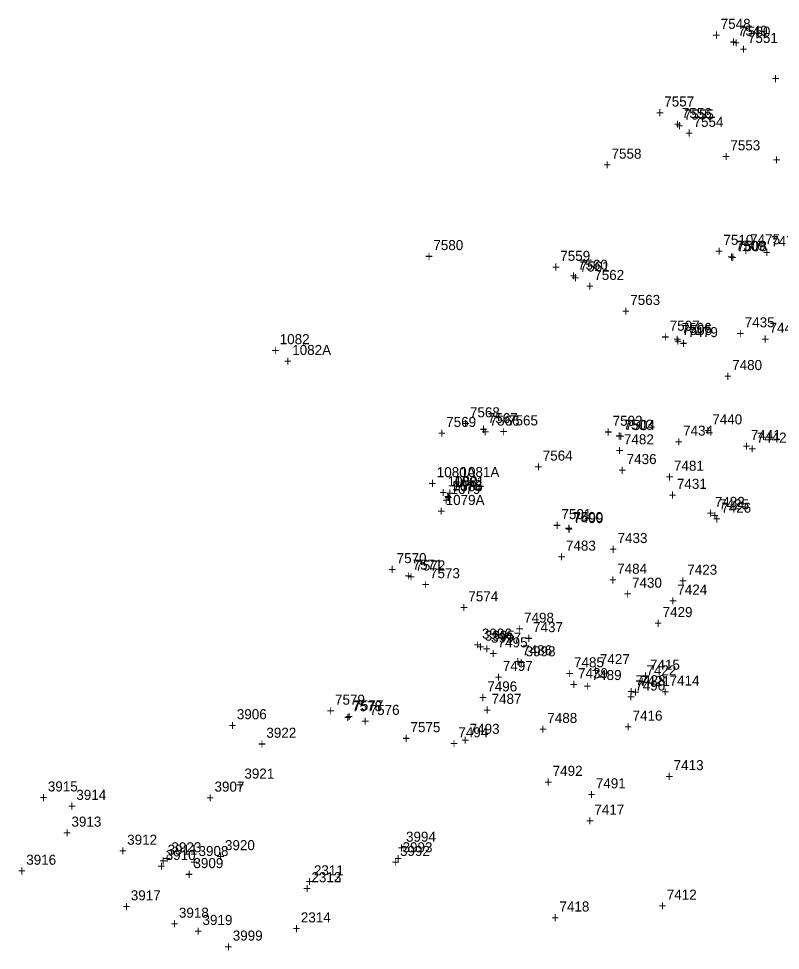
# Model space of a CAD drawing. Extents: x 1136220 to 1137808, y 528804 to 531215.
# Drawn here: x 1137427.4 to 1137616.8, y 530896.4 to 531128 of the extents above; entities that cross this region are included whole.
import ezdxf

# ---------------------------------------------------------------- set-up
doc = ezdxf.new("R2010")
doc.units = 0
for name, color, linetype in [('S_Buildings_SillElevation', 7, 'Continuous'), ('S_Curb_Type_1', 7, 'Continuous'), ('S_Drainage_CB', 7, 'Continuous'), ('S_Drainage_Culvert_Top', 7, 'Continuous'), ('S_Drainage_Invert', 7, 'Continuous'), ('S_Drainage_Sump', 7, 'Continuous'), ('S_Fencing_PostAndRail', 7, 'Continuous'), ('S_Ground_Elevation', 7, 'Continuous'), ('S_Ground_SpotElevation', 7, 'Continuous'), ('S_Property_Walkways', 7, 'Continuous'), ('S_Roadway_Centerline', 7, 'Continuous'), ('S_Roadway_Edge_Pavement', 7, 'Continuous'), ('S_Roadway_Edge_TW', 7, 'Continuous'), ('S_Roadway_Monument', 7, 'Continuous'), ('S_Roadway_Sidewalks', 7, 'Continuous'), ('S_Traffic_Sign_SinglePost', 7, 'Continuous'), ('S_Trees_Decid_Pay', 7, 'Continuous'), ('S_Utilities_Hydrant', 7, 'Continuous'), ('S_Utilities_Pole_Power', 7, 'Continuous'), ('S_Utilities_UG_Sanitary_MH', 7, 'Continuous'), ('S_Utilities_UG_Water_Gate', 7, 'Continuous'), ('S_Utilities_UG_Water_Line', 7, 'Continuous'), ('S_Utilities_UG_Water_Shutoff', 7, 'Continuous')]:
    doc.layers.add(name, color=color, linetype=linetype)

msp = doc.modelspace()

# ---------------------------------------------------------------- texts
at = {"layer": 'S_Buildings_SillElevation'}
for s, p in [('3923', (1137465.36, 530920.75)), ('+', (1137463.29, 530918))]:
    msp.add_text(s, height=2.5, dxfattribs=at).set_placement(p)
at = {"layer": 'S_Curb_Type_1'}
for s, p in [('7549', (1137606.2, 531123.72)), ('+', (1137604.14, 531120.97)), ('7556', (1137592.27, 531103.27)), ('+', (1137590.21, 531100.52)), ('7508', (1137606, 531070.17)), ('+', (1137603.94, 531067.42)), ('7560', (1137566.42, 531065.57)), ('+', (1137564.36, 531062.82)), ('7505', (1137592.37, 531049.33)), ('+', (1137590.31, 531046.58)), ('7567', (1137544.02, 531027.43)), ('7504', (1137578.16, 531025.7)), ('+', (1137541.96, 531024.68)), ('+', (1137576.09, 531022.95)), ('7499', (1137565.33, 531002.59)), ('+', (1137563.27, 530999.84)), ('7571', (1137525.34, 530991.02)), ('+', (1137523.28, 530988.27)), ('7498', (1137553.03, 530977.83)), ('+', (1137550.97, 530975.08)), ('7497', (1137547.76, 530965.84)), ('+', (1137545.7, 530963.09)), ('7578', (1137510.29, 530955.82)), ('+', (1137508.23, 530953.07))]:
    msp.add_text(s, height=2.5, dxfattribs=at).set_placement(p)
at = {"layer": 'S_Drainage_CB'}
for s, p in [('7586', (1137535.3, 531010.5)), ('+', (1137533.24, 531007.75))]:
    msp.add_text(s, height=2.5, dxfattribs=at).set_placement(p)
at = {"layer": 'S_Drainage_Culvert_Top'}
for s, p in [('1082A', (1137495.39, 531044.37)), ('+', (1137493.33, 531041.62)), ('1080A', (1137531.33, 531014)), ('1081A', (1137537.23, 531014.04)), ('+', (1137529.27, 531011.25)), ('+', (1137535.17, 531011.29)), ('1079A', (1137533.54, 531007.09)), ('+', (1137531.48, 531004.34)), ('2313', (1137500.16, 530913.31)), ('+', (1137498.1, 530910.56)), ('2314', (1137497.53, 530903.32)), ('+', (1137495.47, 530900.57))]:
    msp.add_text(s, height=2.5, dxfattribs=at).set_placement(p)
at = {"layer": 'S_Drainage_Invert'}
for s, p in [('1082', (1137492.27, 531047.06)), ('+', (1137490.21, 531044.31)), ('1080', (1137534.02, 531011.73)), ('1081', (1137535.69, 531011.59)), ('+', (1137531.96, 531008.98)), ('+', (1137533.63, 531008.84)), ('1079', (1137534.76, 531009.81)), ('+', (1137532.7, 531007.06)), ('2312', (1137500.16, 530913.31)), ('+', (1137498.1, 530910.56))]:
    msp.add_text(s, height=2.5, dxfattribs=at).set_placement(p)
at = {"layer": 'S_Drainage_Sump'}
for s, p in [('1078', (1137535.17, 531010.75)), ('+', (1137533.11, 531008))]:
    msp.add_text(s, height=2.5, dxfattribs=at).set_placement(p)
at = {"layer": 'S_Fencing_PostAndRail'}
for s, p in [('7425', (1137601.53, 531005.98)), ('+', (1137599.47, 531003.23)), ('7424', (1137591.15, 530984.81)), ('+', (1137589.09, 530982.06)), ('7421', (1137581.86, 530962.08)), ('+', (1137579.8, 530959.33))]:
    msp.add_text(s, height=2.5, dxfattribs=at).set_placement(p)
at = {"layer": 'S_Ground_Elevation'}
for s, p in [('7475', (1137609.26, 531071.88)), ('+', (1137607.2, 531069.13)), ('7479', (1137593.78, 531048.81)), ('+', (1137591.72, 531046.06)), ('7480', (1137604.78, 531040.62)), ('+', (1137602.72, 531037.87)), ('7442', (1137610.87, 531022.59)), ('7482', (1137577.87, 531022.16)), ('+', (1137575.81, 531019.41)), ('+', (1137608.8, 531019.84)), ('7481', (1137590.31, 531015.6)), ('+', (1137588.25, 531012.85)), ('7426', (1137602.06, 531005.16)), ('+', (1137600, 531002.41)), ('7483', (1137563.45, 530995.73)), ('+', (1137561.39, 530992.98)), ('7484', (1137576.19, 530989.99)), ('7423', (1137593.62, 530989.75)), ('+', (1137574.13, 530987.24)), ('+', (1137591.56, 530987)), ('7486', (1137552.59, 530969.72)), ('7485', (1137565.46, 530966.73)), ('+', (1137550.53, 530966.97)), ('7422', (1137583.46, 530964.73)), ('7415', (1137584.35, 530966.13)), ('+', (1137563.4, 530963.98)), ('+', (1137582.29, 530963.38)), ('7414', (1137589.23, 530962.2)), ('+', (1137581.4, 530961.98)), ('7487', (1137544.96, 530957.66)), ('+', (1137587.17, 530959.45)), ('3906', (1137481.61, 530953.83)), ('+', (1137542.9, 530954.91)), ('7488', (1137558.82, 530952.89)), ('7416', (1137580.02, 530953.47)), ('+', (1137479.55, 530951.08)), ('+', (1137556.76, 530950.14)), ('+', (1137577.96, 530950.72)), ('7413', (1137590.24, 530941.17)), ('+', (1137588.17, 530938.42)), ('3915', (1137434.62, 530935.88)), ('3907', (1137476.06, 530935.83)), ('+', (1137432.56, 530933.13)), ('3914', (1137441.7, 530933.79)), ('+', (1137474, 530933.08)), ('+', (1137439.64, 530931.04)), ('7417', (1137570.52, 530930.12)), ('3913', (1137440.49, 530927.13)), ('+', (1137568.45, 530927.37)), ('+', (1137438.43, 530924.38)), ('3912', (1137454.35, 530922.64)), ('+', (1137452.29, 530919.89)), ('3910', (1137463.93, 530918.84)), ('3911', (1137464.39, 530920.15)), ('3908', (1137472.09, 530919.82)), ('+', (1137462.33, 530917.4)), ('+', (1137470.03, 530917.07)), ('3909', (1137470.82, 530916.82)), ('+', (1137461.87, 530916.09)), ('+', (1137468.76, 530914.07)), ('7412', (1137588.53, 530908.98)), ('7418', (1137561.84, 530906.03)), ('+', (1137586.47, 530906.23)), ('+', (1137559.78, 530903.28))]:
    msp.add_text(s, height=2.5, dxfattribs=at).set_placement(p)
at = {"layer": 'S_Ground_SpotElevation'}
for s, p in [('3922', (1137488.96, 530949.22)), ('+', (1137486.9, 530946.47)), ('3921', (1137483.49, 530939.07)), ('+', (1137481.43, 530936.32)), ('3920', (1137478.66, 530921.28)), ('+', (1137476.6, 530918.53)), ('3916', (1137429.25, 530917.66)), ('+', (1137427.19, 530914.91)), ('3917', (1137455.25, 530908.81)), ('+', (1137453.19, 530906.06)), ('3918', (1137467.21, 530904.49)), ('3919', (1137473.08, 530902.69)), ('+', (1137465.15, 530901.74)), ('+', (1137471.02, 530899.94))]:
    msp.add_text(s, height=2.5, dxfattribs=at).set_placement(p)
at = {"layer": 'S_Property_Walkways'}
for s, p in [('7445', (1137614.09, 531049.88)), ('+', (1137612.03, 531047.13)), ('7440', (1137599.84, 531027.12)), ('+', (1137597.78, 531024.37)), ('7441', (1137609.43, 531023.26)), ('+', (1137607.37, 531020.51)), ('7431', (1137591.04, 531011.1)), ('+', (1137588.98, 531008.35)), ('7432', (1137600.47, 531006.6)), ('+', (1137598.41, 531003.85)), ('7430', (1137579.88, 530986.52)), ('+', (1137577.82, 530983.77)), ('7429', (1137587.48, 530979.22)), ('+', (1137585.42, 530976.47)), ('7427', (1137571.89, 530967.52)), ('+', (1137569.82, 530964.77)), ('7489', (1137569.85, 530963.57)), ('7428', (1137580.78, 530962.27)), ('+', (1137567.79, 530960.82)), ('7490', (1137580.7, 530960.97)), ('+', (1137578.64, 530958.22)), ('+', (1137578.72, 530959.52)), ('7492', (1137560.15, 530939.76)), ('+', (1137558.09, 530937.01)), ('7491', (1137570.88, 530936.65)), ('+', (1137568.82, 530933.9))]:
    msp.add_text(s, height=2.5, dxfattribs=at).set_placement(p)
at = {"layer": 'S_Roadway_Centerline'}
for s, p in [('+', (1137614.6, 531111.86)), ('7553', (1137604.34, 531095.24)), ('+', (1137602.28, 531092.49)), ('7563', (1137579.44, 531056.81)), ('+', (1137577.38, 531054.06)), ('7564', (1137557.68, 531018.11)), ('+', (1137555.62, 531015.36)), ('7574', (1137539.18, 530983.15)), ('+', (1137537.12, 530980.4)), ('7575', (1137524.79, 530950.62)), ('+', (1137522.73, 530947.87))]:
    msp.add_text(s, height=2.5, dxfattribs=at).set_placement(p)
at = {"layer": 'S_Roadway_Edge_Pavement'}
for s, p in [('7550', (1137606.85, 531123.49)), ('+', (1137604.79, 531120.74)), ('7555', (1137592.78, 531102.9)), ('+', (1137590.72, 531100.15)), ('7509', (1137605.68, 531070.28)), ('+', (1137603.62, 531067.53)), ('7561', (1137566.88, 531065.12)), ('+', (1137564.82, 531062.37)), ('7506', (1137592.22, 531049.85)), ('+', (1137590.15, 531047.1)), ('7566', (1137544.47, 531026.8)), ('7503', (1137577.77, 531025.78)), ('+', (1137542.41, 531024.05)), ('+', (1137575.71, 531023.03)), ('7500', (1137565.23, 531002.82)), ('+', (1137563.17, 531000.07)), ('7572', (1137526.01, 530990.8)), ('+', (1137523.95, 530988.05)), ('7496', (1137543.89, 530960.74)), ('+', (1137541.83, 530957.99)), ('7577', (1137510.6, 530956.04)), ('+', (1137508.54, 530953.29)), ('7493', (1137539.51, 530950.19)), ('+', (1137537.44, 530947.44))]:
    msp.add_text(s, height=2.5, dxfattribs=at).set_placement(p)
at = {"layer": 'S_Roadway_Edge_TW'}
for s, p in [('7551', (1137608.7, 531121.94)), ('+', (1137606.64, 531119.19)), ('7554', (1137595.18, 531101.08)), ('+', (1137593.12, 531098.33)), ('+', (1137614.85, 531091.68)), ('7510', (1137602.6, 531071.74)), ('+', (1137600.54, 531068.99)), ('7562', (1137570.49, 531063.02)), ('+', (1137568.43, 531060.27)), ('7507', (1137589.25, 531050.39)), ('+', (1137587.19, 531047.64)), ('7565', (1137549.05, 531026.86)), ('7502', (1137575.06, 531026.77)), ('+', (1137546.99, 531024.11)), ('+', (1137573, 531024.02)), ('7501', (1137562.33, 531003.57)), ('+', (1137560.27, 531000.82)), ('7573', (1137529.65, 530988.88)), ('+', (1137527.59, 530986.13)), ('7495', (1137546.47, 530971.69)), ('+', (1137544.41, 530968.94)), ('7576', (1137514.64, 530954.9)), ('+', (1137512.58, 530952.15)), ('7494', (1137536.7, 530949.33)), ('+', (1137534.64, 530946.58))]:
    msp.add_text(s, height=2.5, dxfattribs=at).set_placement(p)
at = {"layer": 'S_Roadway_Monument'}
for s, p in [('7580', (1137530.48, 531070.44)), ('+', (1137528.42, 531067.69))]:
    msp.add_text(s, height=2.5, dxfattribs=at).set_placement(p)
at = {"layer": 'S_Roadway_Sidewalks'}
for s, p in [('7548', (1137601.94, 531125.44)), ('+', (1137599.88, 531122.69)), ('7557', (1137587.9, 531106.14)), ('+', (1137585.84, 531103.39)), ('7559', (1137562.04, 531067.77)), ('+', (1137559.98, 531065.02)), ('7568', (1137539.58, 531028.87)), ('+', (1137537.52, 531026.12)), ('7570', (1137521.35, 530992.62)), ('+', (1137519.29, 530989.87)), ('7579', (1137506.03, 530957.44)), ('+', (1137503.97, 530954.69))]:
    msp.add_text(s, height=2.5, dxfattribs=at).set_placement(p)
at = {"layer": 'S_Traffic_Sign_SinglePost'}
for s, p in [('7558', (1137574.79, 531093.16)), ('+', (1137572.73, 531090.41)), ('7569', (1137533.68, 531026.48)), ('+', (1137531.62, 531023.73)), ('7436', (1137578.55, 531017.25)), ('+', (1137576.49, 531014.5)), ('7439', (1137566.46, 530964.03)), ('+', (1137564.4, 530961.28))]:
    msp.add_text(s, height=2.5, dxfattribs=at).set_placement(p)
at = {"layer": 'S_Trees_Decid_Pay'}
for s, p in [('7435', (1137607.9, 531051.24)), ('+', (1137605.84, 531048.49)), ('7434', (1137592.58, 531024.32)), ('+', (1137590.52, 531021.57)), ('7433', (1137576.28, 530997.62)), ('+', (1137574.22, 530994.87))]:
    msp.add_text(s, height=2.5, dxfattribs=at).set_placement(p)
at = {"layer": 'S_Utilities_Hydrant'}
for s, p in [('3998', (1137553.42, 530969.46)), ('+', (1137551.36, 530966.71))]:
    msp.add_text(s, height=2.5, dxfattribs=at).set_placement(p)
at = {"layer": 'S_Utilities_Pole_Power'}
for s, p in [('7476', (1137614.49, 531071.42)), ('+', (1137612.43, 531068.67)), ('7437', (1137555.27, 530975.48)), ('+', (1137553.21, 530972.73))]:
    msp.add_text(s, height=2.5, dxfattribs=at).set_placement(p)
at = {"layer": 'S_Utilities_UG_Sanitary_MH'}
for s, p in [('2311', (1137500.78, 530915.02)), ('+', (1137498.72, 530912.27))]:
    msp.add_text(s, height=2.5, dxfattribs=at).set_placement(p)
at = {"layer": 'S_Utilities_UG_Water_Gate'}
for s, p in [('3995', (1137543.26, 530973.35)), ('+', (1137541.2, 530970.6)), ('3994', (1137523.68, 530923.38)), ('+', (1137521.61, 530920.63))]:
    msp.add_text(s, height=2.5, dxfattribs=at).set_placement(p)
at = {"layer": 'S_Utilities_UG_Water_Line'}
for s, p in [('3996', (1137542.58, 530973.87)), ('3997', (1137544.84, 530972.86)), ('+', (1137540.52, 530971.12)), ('+', (1137542.78, 530970.11)), ('3993', (1137522.82, 530920.75)), ('3992', (1137522.19, 530919.84)), ('+', (1137520.13, 530917.09)), ('+', (1137520.76, 530918))]:
    msp.add_text(s, height=2.5, dxfattribs=at).set_placement(p)
at = {"layer": 'S_Utilities_UG_Water_Shutoff'}
for s, p in [('3999', (1137480.59, 530898.81)), ('+', (1137478.53, 530896.06))]:
    msp.add_text(s, height=2.5, dxfattribs=at).set_placement(p)

doc.saveas('drawing.dxf')
